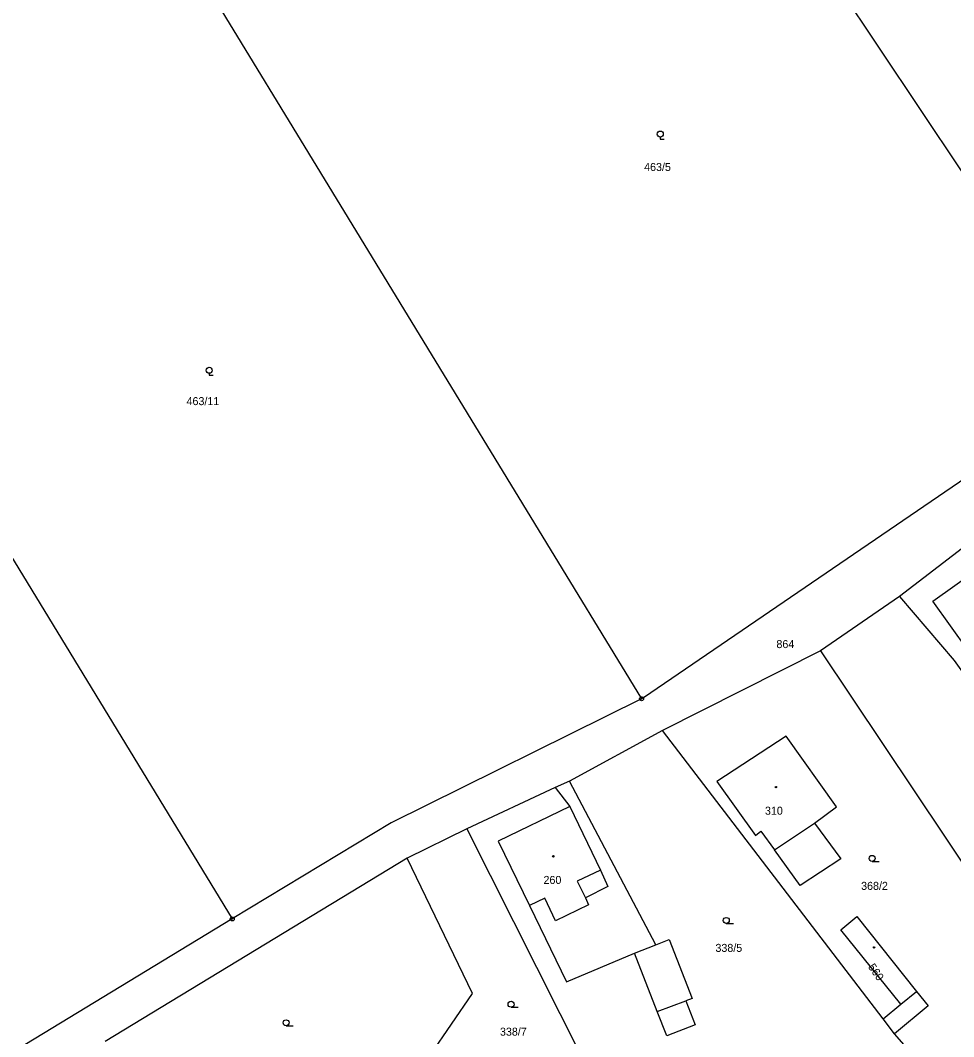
# Model space of a CAD drawing. Extents: x -745926 to -742978, y -968282 to -965689.
# Drawn here: x -744972.9 to -744856.3, y -966725.4 to -966598.4 of the extents above; entities that cross this region are included whole.
import ezdxf

# ---------------------------------------------------------------- set-up
doc = ezdxf.new("R2010")
doc.units = 0
for name, color, linetype in [('Hranice parcel', 7, 'Continuous'), ('Parcelní čísla', 7, 'Continuous'), ('Vnitřní kresba', 7, 'Continuous'), ('Značky bodu BP', 7, 'Continuous'), ('Značky budov', 7, 'Continuous'), ('Značky kultur', 7, 'Continuous')]:
    doc.layers.add(name, color=color, linetype=linetype)

msp = doc.modelspace()

# ---------------------------------------------------------------- linework, layer by layer
at = {"layer": 'Hranice parcel'}
for p, q in [((-744957.77, -966580.82), (-744895.3, -966683.21)), ((-745011.89, -966603.4), (-744946.43, -966710.72)), ((-744849.16, -966659.7), (-744863.06, -966670.44)), ((-744863.06, -966670.44), (-744872.94, -966677.23)), ((-744872.94, -966677.23), (-744892.68, -966687.18)), ((-744872.94, -966677.23), (-744841.78, -966723.83)), ((-744892.68, -966687.18), (-744904.32, -966693.52)), ((-744865.12, -966723.19), (-744892.68, -966687.18)), ((-744904.32, -966693.52), (-744906.08, -966694.31)), ((-744906.08, -966694.31), (-744917.15, -966699.46)), ((-744917.15, -966699.46), (-744924.57, -966703.11)), ((-744917.15, -966699.46), (-744900.1, -966733.23)), ((-744924.57, -966703.11), (-744962.31, -966726.05)), ((-744946.43, -966710.72), (-744977.68, -966729.66)), ((-744865.12, -966723.19), (-744862.89, -966721.38)), ((-744863.71, -966725.09), (-744865.12, -966723.19)), ((-744861.01, -966728.18), (-744863.71, -966725.09))]:
    msp.add_line(p, q, dxfattribs=at)
for points in [[(-744870.73, -966594.19), (-744840.02, -966640.22), (-744839.84, -966645.38)], [(-744839.84, -966645.38), (-744895.06, -966683.09), (-744895.3, -966683.21)], [(-744863.06, -966670.44), (-744856.26, -966678.45), (-744854.05, -966681.52), (-744851.84, -966683.93), (-744843.15, -966691.5), (-744833.83, -966683.07), (-744829.99, -966679.45)], [(-744895.3, -966683.21), (-744926.6, -966698.7), (-744946.43, -966710.72)], [(-744870.95, -966696.73), (-744877.23, -966687.89), (-744885.9, -966693.53), (-744881.05, -966700.3), (-744880.4, -966699.75), (-744878.7, -966702.1), (-744873.71, -966698.76), (-744870.95, -966696.73)], [(-744906.08, -966694.31), (-744904.28, -966696.68), (-744913.2, -966701.01), (-744909.29, -966709.05), (-744904.68, -966718.57), (-744896.19, -966715), (-744893.53, -966713.96), (-744904.32, -966693.52)], [(-744927.42, -966735.61), (-744926.93, -966735.35), (-744916.41, -966720.03), (-744924.57, -966703.11)], [(-744862.89, -966721.38), (-744870.42, -966712.09), (-744868.41, -966710.4)], [(-744868.41, -966710.4), (-744860.96, -966719.8), (-744859.49, -966721.59), (-744863.71, -966725.09)]]:
    msp.add_lwpolyline(points, dxfattribs=at)
at = {"layer": 'Vnitřní kresba'}
for p, q in [((-744858.92, -966671.03), (-744849.09, -966663.96)), ((-744854.5, -966677.18), (-744858.92, -966671.03)), ((-744904.28, -966696.68), (-744900.43, -966704.61)), ((-744873.71, -966698.76), (-744870.42, -966703.21)), ((-744875.48, -966706.55), (-744878.7, -966702.1)), ((-744870.42, -966703.21), (-744875.48, -966706.55)), ((-744900.43, -966704.61), (-744903.33, -966706.02)), ((-744900.43, -966704.61), (-744899.5, -966706.67)), ((-744903.33, -966706.02), (-744902.32, -966708.1)), ((-744899.5, -966706.67), (-744902.32, -966708.1)), ((-744907.4, -966708.13), (-744909.29, -966709.05)), ((-744906.04, -966710.94), (-744907.4, -966708.13)), ((-744901.91, -966708.94), (-744906.04, -966710.94)), ((-744902.32, -966708.1), (-744901.91, -966708.94)), ((-744893.53, -966713.96), (-744891.85, -966713.3)), ((-744891.85, -966713.3), (-744888.98, -966720.65)), ((-744893.34, -966722.31), (-744896.19, -966715)), ((-744862.89, -966721.38), (-744860.96, -966719.8)), ((-744893.34, -966722.31), (-744889.76, -966720.95)), ((-744888.98, -966720.65), (-744889.76, -966720.95)), ((-744889.76, -966720.95), (-744888.6, -966723.94)), ((-744892.16, -966725.33), (-744893.34, -966722.31)), ((-744888.6, -966723.94), (-744892.16, -966725.33))]:
    msp.add_line(p, q, dxfattribs=at)
at = {"layer": 'Značky bodu BP'}
for centre, radius in [((-744895.3, -966683.21), 0.25), ((-744895.3, -966683.21), 0.0152), ((-744946.43, -966710.72), 0.25), ((-744946.43, -966710.72), 0.0152)]:
    msp.add_circle(centre, radius, dxfattribs=at)
at = {"layer": 'Značky budov'}
for centre in [(-744878.51, -966694.25), (-744906.32, -966702.9), (-744866.25, -966714.29)]:
    msp.add_circle(centre, 0.0875, dxfattribs=at)
at = {"layer": 'Značky kultur'}
for p, q in [((-744892.96, -966613.02), (-744892.96, -966613.27)), ((-744892.96, -966613.27), (-744892.46, -966613.27)), ((-744949.32, -966642.53), (-744949.32, -966642.78)), ((-744949.32, -966642.78), (-744948.82, -966642.78)), ((-744866.49, -966703.54), (-744865.61, -966703.54)), ((-744884.71, -966711.29), (-744883.83, -966711.29)), ((-744911.6, -966721.76), (-744910.72, -966721.76)), ((-744939.71, -966724.08), (-744938.83, -966724.08))]:
    msp.add_line(p, q, dxfattribs=at)
for centre in [(-744892.96, -966612.65), (-744949.32, -966642.16), (-744866.49, -966703.16), (-744884.71, -966710.91), (-744911.6, -966721.38), (-744939.71, -966723.7)]:
    msp.add_circle(centre, 0.375, dxfattribs=at)

# ---------------------------------------------------------------- texts
at = {"layer": 'Parcelní čísla'}
for s, p in [('463/5', (-744894.98, -966617.26)), ('463/11', (-744952.15, -966646.52)), ('864', (-744878.45, -966676.88)), ('310', (-744879.88, -966697.7)), ('260', (-744907.55, -966706.35)), ('368/2', (-744867.87, -966707.09)), ('338/5', (-744886.07, -966714.84)), ('338/7', (-744912.99, -966725.31))]:
    msp.add_text(s, height=1, dxfattribs=at).set_placement(p)
msp.add_text('560', height=1, rotation=305, dxfattribs=at).set_placement((-744867.05, -966716.73))

doc.saveas('drawing.dxf')
